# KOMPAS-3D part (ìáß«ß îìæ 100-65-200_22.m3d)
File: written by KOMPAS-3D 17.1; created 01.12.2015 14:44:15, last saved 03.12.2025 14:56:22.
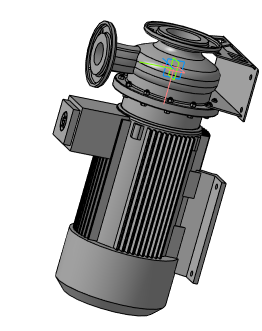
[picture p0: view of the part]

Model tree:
1. Операция без истории:4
